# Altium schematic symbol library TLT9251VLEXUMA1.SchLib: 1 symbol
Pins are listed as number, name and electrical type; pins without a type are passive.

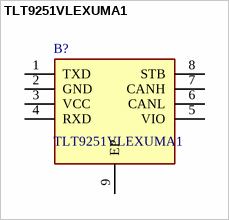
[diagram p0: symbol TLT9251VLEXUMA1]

## TLT9251VLEXUMA1
designator B?
CAN Interface IC; Manufacturer_Name: Infineon; Geometry.Height: 1.1mm
footprint SON65P300X300X110-9N
pins: 1 TXD, 2 GND, 3 VCC, 4 RXD, 5 VIO, 6 CANL, 7 CANH, 8 STB, 9 EP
